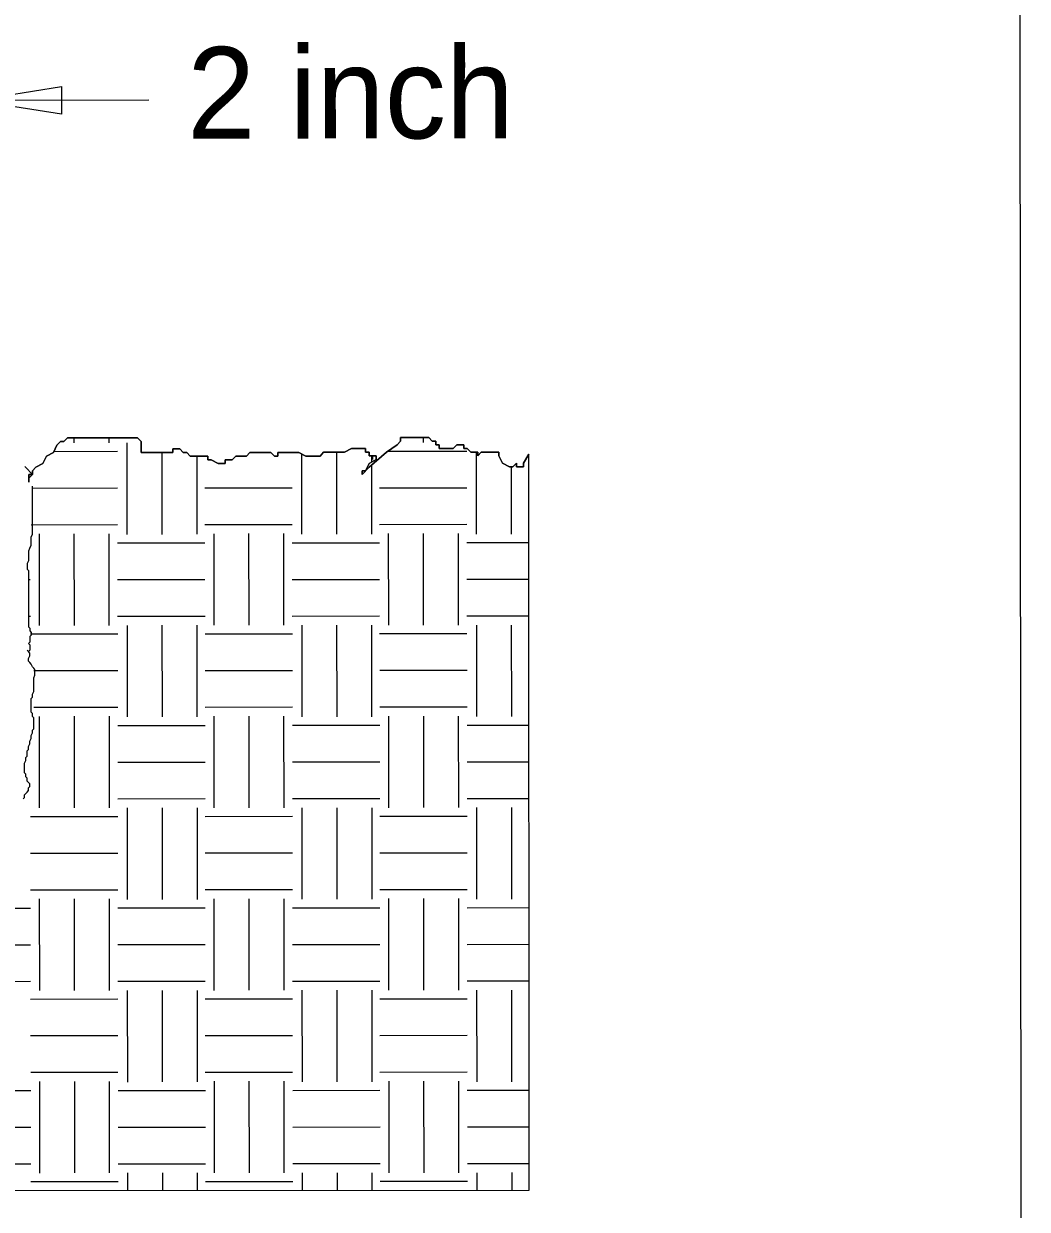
# Model space of a CAD drawing. Extents: x 816132 to 817815, y 885694 to 886789.
# Drawn here: x 816943.9 to 817017.4, y 886385.8 to 886472.6 of the extents above; entities that cross this region are included whole.
import ezdxf

# ---------------------------------------------------------------- set-up
doc = ezdxf.new("R2010")
doc.units = 0
doc.layers.add('Silt Fence Coir Fiber Wattle Break Detail CELL', color=7, linetype='Continuous')

msp = doc.modelspace()

# ---------------------------------------------------------------- linework, layer by layer
at = {"layer": 'Silt Fence Coir Fiber Wattle Break Detail CELL'}
for p, q in [((817017.371, 885756.766), (817016.667, 886743.224)), ((816953.074, 886467.002), (816940.291, 886466.992)), ((816947.593, 886442.299), (816947.594, 886441.931)), ((816950.15, 886442.301), (816950.15, 886441.932)), ((816951.475, 886441.934), (816951.48, 886435.229)), ((816973.158, 886442.32), (816973.158, 886441.951)), ((816946.142, 886441.306), (816950.79, 886441.309)), ((816954.032, 886441.226), (816954.036, 886435.231)), ((816956.589, 886440.959), (816956.593, 886435.234)), ((816964.258, 886441.133), (816964.262, 886435.239)), ((816966.815, 886441.236), (816966.819, 886435.242)), ((816969.371, 886440.969), (816969.371, 886440.52)), ((816970.607, 886441.326), (816976.354, 886441.33)), ((816977.04, 886441.244), (816977.044, 886435.25)), ((816980.917, 886387.232), (816980.879, 886441.113)), ((816969.371, 886440.304), (816969.375, 886435.244)), ((816979.597, 886440.169), (816979.6, 886435.252)), ((816944.532, 886438.623), (816950.792, 886438.628)), ((816957.183, 886438.634), (816963.574, 886438.638)), ((816969.965, 886438.643), (816976.357, 886438.648)), ((816944.458, 886435.941), (816950.793, 886435.946)), ((816957.185, 886435.952), (816963.576, 886435.957)), ((816969.967, 886435.962), (816976.358, 886435.967)), ((816945.042, 886435.272), (816945.047, 886428.568)), ((816947.599, 886435.273), (816947.603, 886428.57)), ((816950.155, 886435.275), (816950.16, 886428.571)), ((816957.825, 886435.281), (816957.829, 886428.578)), ((816960.381, 886435.283), (816960.386, 886428.579)), ((816962.938, 886435.286), (816962.942, 886428.581)), ((816963.577, 886434.615), (816969.968, 886434.62)), ((816970.606, 886435.291), (816970.612, 886428.587)), ((816973.163, 886435.294), (816973.168, 886428.589)), ((816975.719, 886435.296), (816975.724, 886428.592)), ((816976.359, 886434.625), (816980.883, 886434.63)), ((816950.795, 886434.606), (816957.185, 886434.611)), ((816944.345, 886431.919), (816944.406, 886431.919)), ((816950.796, 886431.924), (816957.187, 886431.929)), ((816963.579, 886431.934), (816969.97, 886431.939)), ((816976.361, 886431.944), (816980.885, 886431.948)), ((816944.27, 886429.238), (816944.407, 886429.237)), ((816950.798, 886429.242), (816957.19, 886429.247)), ((816951.484, 886428.572), (816951.489, 886421.868)), ((816954.041, 886428.575), (816954.046, 886421.87)), ((816956.598, 886428.577), (816956.602, 886421.873)), ((816963.58, 886429.252), (816969.972, 886429.257)), ((816964.267, 886428.583), (816964.272, 886421.878)), ((816966.824, 886428.585), (816966.828, 886421.881)), ((816969.38, 886428.586), (816969.385, 886421.883)), ((816976.363, 886429.263), (816980.887, 886429.266)), ((816977.049, 886428.593), (816977.054, 886421.888)), ((816979.605, 886428.595), (816979.611, 886421.891)), ((816944.408, 886427.944), (816950.799, 886427.948)), ((816957.19, 886427.953), (816963.582, 886427.958)), ((816969.973, 886427.964), (816976.364, 886427.969)), ((816944.651, 886425.262), (816950.801, 886425.267)), ((816957.192, 886425.272), (816963.583, 886425.276)), ((816969.975, 886425.282), (816976.366, 886425.287)), ((816944.653, 886422.581), (816950.803, 886422.585)), ((816957.194, 886422.59), (816963.585, 886422.596)), ((816969.976, 886422.601), (816976.368, 886422.606)), ((816945.052, 886421.911), (816945.056, 886415.206)), ((816947.608, 886421.912), (816947.613, 886415.209)), ((816950.164, 886421.914), (816950.169, 886415.21)), ((816957.834, 886421.92), (816957.839, 886415.217)), ((816960.39, 886421.922), (816960.395, 886415.218)), ((816962.947, 886421.924), (816962.952, 886415.22)), ((816970.616, 886421.93), (816970.621, 886415.226)), ((816973.172, 886421.932), (816973.178, 886415.228)), ((816975.729, 886421.935), (816975.734, 886415.23)), ((816950.804, 886421.245), (816957.195, 886421.25)), ((816963.587, 886421.254), (816969.977, 886421.259)), ((816976.369, 886421.264), (816980.893, 886421.268)), ((816950.806, 886418.563), (816957.197, 886418.568)), ((816963.588, 886418.573), (816969.979, 886418.578)), ((816976.371, 886418.583), (816980.895, 886418.587)), ((816950.808, 886415.881), (816957.199, 886415.886)), ((816963.59, 886415.891), (816969.982, 886415.896)), ((816976.372, 886415.901), (816980.896, 886415.905)), ((816951.494, 886415.211), (816951.499, 886408.507)), ((816954.05, 886415.213), (816954.055, 886408.509)), ((816956.607, 886415.216), (816956.612, 886408.511)), ((816964.276, 886415.221), (816964.281, 886408.517)), ((816966.833, 886415.224), (816966.838, 886408.519)), ((816969.39, 886415.225), (816969.394, 886408.522)), ((816977.059, 886415.232), (816977.064, 886408.527)), ((816979.616, 886415.233), (816979.62, 886408.53)), ((816944.418, 886414.582), (816950.809, 886414.587)), ((816957.2, 886414.592), (816963.591, 886414.597)), ((816969.982, 886414.602), (816976.373, 886414.607)), ((816944.42, 886411.901), (816950.811, 886411.906)), ((816957.202, 886411.91), (816963.593, 886411.915)), ((816969.984, 886411.92), (816976.376, 886411.926)), ((816944.421, 886409.219), (816950.812, 886409.224)), ((816957.204, 886409.229), (816963.595, 886409.234)), ((816969.986, 886409.239), (816976.377, 886409.244)), ((816941.4, 886407.875), (816944.423, 886407.879)), ((816945.061, 886408.55), (816945.066, 886401.845)), ((816947.618, 886408.551), (816947.622, 886401.847)), ((816950.174, 886408.553), (816950.179, 886401.849)), ((816950.814, 886407.884), (816957.204, 886407.889)), ((816957.844, 886408.559), (816957.848, 886401.855)), ((816960.4, 886408.561), (816960.405, 886401.857)), ((816962.956, 886408.563), (816962.961, 886401.859)), ((816963.596, 886407.893), (816969.987, 886407.898)), ((816970.626, 886408.569), (816970.631, 886401.865)), ((816973.182, 886408.571), (816973.187, 886401.867)), ((816975.739, 886408.573), (816975.744, 886401.869)), ((816976.379, 886407.903), (816980.902, 886407.907)), ((816938.033, 886405.191), (816944.425, 886405.197)), ((816950.815, 886405.202), (816957.207, 886405.207)), ((816963.598, 886405.212), (816969.989, 886405.217)), ((816976.38, 886405.221), (816980.904, 886405.225)), ((816938.035, 886402.509), (816944.426, 886402.515)), ((816950.818, 886402.52), (816957.209, 886402.525)), ((816963.599, 886402.53), (816969.991, 886402.535)), ((816976.382, 886402.54), (816980.906, 886402.543)), ((816951.504, 886401.85), (816951.508, 886395.146)), ((816954.06, 886401.852), (816954.065, 886395.148)), ((816956.617, 886401.855), (816956.621, 886395.15)), ((816964.286, 886401.86), (816964.291, 886395.156)), ((816966.843, 886401.863), (816966.847, 886395.158)), ((816969.399, 886401.864), (816969.404, 886395.16)), ((816977.069, 886401.871), (816977.073, 886395.166)), ((816979.625, 886401.872), (816979.63, 886395.168)), ((816944.428, 886401.221), (816950.818, 886401.226)), ((816957.209, 886401.231), (816963.601, 886401.236)), ((816969.992, 886401.241), (816976.383, 886401.246)), ((816944.429, 886398.54), (816950.82, 886398.545)), ((816957.212, 886398.549), (816963.603, 886398.554)), ((816969.993, 886398.559), (816976.385, 886398.564)), ((816944.431, 886395.858), (816950.822, 886395.863)), ((816957.213, 886395.868), (816963.604, 886395.873)), ((816969.996, 886395.878), (816976.387, 886395.883)), ((816945.07, 886395.188), (816945.075, 886388.484)), ((816947.627, 886395.19), (816947.632, 886388.486)), ((816950.184, 886395.192), (816950.188, 886388.487)), ((816957.853, 886395.198), (816957.858, 886388.494)), ((816960.41, 886395.2), (816960.414, 886388.495)), ((816962.966, 886395.202), (816962.971, 886388.498)), ((816970.636, 886395.208), (816970.64, 886388.503)), ((816973.192, 886395.21), (816973.197, 886388.506)), ((816975.748, 886395.212), (816975.753, 886388.508)), ((816938.04, 886394.512), (816944.432, 886394.517)), ((816950.823, 886394.522), (816957.215, 886394.527)), ((816963.606, 886394.532), (816969.996, 886394.537)), ((816976.388, 886394.542), (816980.912, 886394.546)), ((816938.043, 886391.83), (816944.434, 886391.835)), ((816950.825, 886391.84), (816957.217, 886391.846)), ((816963.607, 886391.851), (816969.999, 886391.855)), ((816976.39, 886391.86), (816980.913, 886391.864)), ((816938.045, 886389.148), (816944.436, 886389.153)), ((816950.827, 886389.159), (816957.218, 886389.164)), ((816963.609, 886389.169), (816970.001, 886389.174)), ((816976.391, 886389.179), (816980.916, 886389.182)), ((816944.437, 886387.86), (816950.828, 886387.865)), ((816951.513, 886388.489), (816951.514, 886387.208)), ((816954.069, 886388.491), (816954.07, 886387.211)), ((816956.626, 886388.493), (816956.627, 886387.213)), ((816957.219, 886387.87), (816963.61, 886387.875)), ((816964.295, 886388.499), (816964.296, 886387.219)), ((816966.852, 886388.501), (816966.853, 886387.221)), ((816969.409, 886388.503), (816969.409, 886387.222)), ((816970.001, 886387.88), (816976.393, 886387.885)), ((816977.078, 886388.509), (816977.079, 886387.229)), ((816979.635, 886388.511), (816979.635, 886387.23)), ((816904.941, 886387.171), (816980.917, 886387.232))]:
    msp.add_line(p, q, dxfattribs=at)
msp.add_lwpolyline([(816946.683, 886465.991), (816940.291, 886466.992), (816946.682, 886468.002)], close=True, dxfattribs=at)
for points in [[(816943.999, 886440.191), (816944.047, 886440.14), (816944.56, 886439.602), (816944.304, 886439.602), (816944.304, 886439.333), (816944.305, 886439.063), (816944.304, 886439.333), (816944.56, 886439.602), (816944.56, 886439.872), (816944.816, 886440.142), (816945.331, 886440.412), (816945.586, 886440.95), (816946.1, 886441.219), (816946.356, 886441.76), (816946.613, 886442.029), (816946.87, 886442.029), (816947.125, 886442.299), (816947.382, 886442.3), (816947.639, 886442.3), (816948.152, 886442.3), (816948.409, 886442.3), (816948.923, 886442.3), (816949.179, 886442.301), (816949.436, 886442.301), (816949.692, 886442.302), (816949.949, 886442.301), (816950.206, 886442.301), (816950.977, 886442.302), (816951.232, 886442.303), (816951.489, 886442.303), (816951.746, 886442.303), (816952.003, 886442.302), (816952.259, 886442.303), (816952.516, 886442.033), (816952.516, 886441.494), (816952.516, 886441.225), (816952.773, 886441.225), (816953.287, 886441.225), (816953.8, 886441.226), (816954.056, 886441.226), (816954.313, 886441.226), (816954.57, 886441.226), (816954.827, 886441.226), (816954.827, 886441.496), (816955.083, 886441.496), (816955.34, 886441.496), (816955.597, 886441.227), (816955.853, 886441.228), (816956.11, 886440.958), (816956.367, 886440.959), (816956.624, 886440.959), (816956.881, 886440.959), (816957.136, 886440.96), (816957.394, 886440.96), (816957.393, 886440.689), (816957.651, 886440.689), (816958.164, 886440.422), (816958.421, 886440.423), (816958.677, 886440.422), (816958.677, 886440.691), (816958.934, 886440.691), (816959.19, 886440.691), (816959.447, 886440.962), (816959.704, 886440.961), (816959.96, 886440.961), (816960.217, 886440.962), (816960.473, 886441.231), (816960.987, 886441.231), (816961.244, 886441.232), (816961.5, 886441.232), (816961.757, 886441.232), (816962.014, 886441.233), (816962.27, 886440.963), (816962.527, 886440.964), (816962.526, 886441.233), (816962.784, 886441.233), (816963.041, 886441.233), (816963.297, 886441.233), (816963.554, 886441.234), (816963.811, 886441.234), (816964.067, 886441.234), (816964.58, 886440.965), (816964.837, 886440.965), (816965.094, 886440.966), (816965.351, 886440.966), (816965.607, 886440.966), (816965.863, 886441.236), (816966.121, 886441.236), (816966.378, 886441.236), (816966.633, 886441.236), (816966.89, 886441.236), (816967.404, 886441.237), (816967.917, 886441.506)], [(816967.917, 886441.506), (816967.404, 886441.237), (816966.89, 886441.236), (816966.633, 886441.236), (816966.378, 886441.236), (816966.121, 886441.236), (816965.863, 886441.236), (816965.607, 886440.966), (816965.351, 886440.966), (816965.094, 886440.966), (816964.837, 886440.965), (816964.58, 886440.965), (816964.067, 886441.234), (816963.811, 886441.234), (816963.554, 886441.234), (816963.297, 886441.233), (816963.041, 886441.233), (816962.784, 886441.233), (816962.526, 886441.233), (816962.527, 886440.964), (816962.27, 886440.963), (816962.014, 886441.233), (816961.757, 886441.232), (816961.5, 886441.232), (816961.244, 886441.232), (816960.987, 886441.231), (816960.473, 886441.231), (816960.217, 886440.962), (816959.96, 886440.961), (816959.704, 886440.961), (816959.447, 886440.962), (816959.19, 886440.691), (816958.934, 886440.691), (816958.677, 886440.691), (816958.677, 886440.422), (816958.421, 886440.423), (816958.164, 886440.422), (816957.651, 886440.689), (816957.393, 886440.689), (816957.394, 886440.96), (816957.136, 886440.96), (816956.881, 886440.959), (816956.624, 886440.959), (816956.367, 886440.959), (816956.11, 886440.958), (816955.853, 886441.228), (816955.597, 886441.227), (816955.34, 886441.496), (816955.083, 886441.496), (816954.827, 886441.496), (816954.827, 886441.226), (816954.57, 886441.226), (816954.313, 886441.226), (816954.056, 886441.226), (816953.8, 886441.226), (816953.287, 886441.225), (816952.773, 886441.225), (816952.516, 886441.225), (816952.516, 886441.494), (816952.516, 886442.033), (816952.259, 886442.303), (816952.003, 886442.302), (816951.746, 886442.303), (816951.489, 886442.303), (816951.232, 886442.303), (816950.977, 886442.302), (816950.206, 886442.301), (816949.949, 886442.301), (816949.692, 886442.302), (816949.436, 886442.301), (816949.179, 886442.301), (816948.923, 886442.3), (816948.409, 886442.3), (816948.152, 886442.3), (816947.639, 886442.3), (816947.382, 886442.3), (816947.125, 886442.299), (816946.87, 886442.029), (816946.613, 886442.029), (816946.356, 886441.76), (816946.1, 886441.219), (816945.586, 886440.95), (816945.331, 886440.412), (816944.816, 886440.142), (816944.56, 886439.872), (816944.56, 886439.602), (816944.304, 886439.333), (816944.305, 886439.063), (816944.304, 886439.333), (816944.304, 886439.602), (816944.56, 886439.602), (816944.047, 886440.14), (816943.999, 886440.191)], [(816967.917, 886441.506), (816968.43, 886441.507), (816968.686, 886441.506), (816968.944, 886441.508), (816968.944, 886441.238), (816969.201, 886441.238), (816969.201, 886440.969), (816969.201, 886441.238), (816969.201, 886440.969), (816969.458, 886440.969), (816969.458, 886440.699), (816969.458, 886440.969), (816969.714, 886440.97), (816969.714, 886440.699), (816969.201, 886440.43), (816968.945, 886439.891), (816968.688, 886439.891), (816968.688, 886439.621), (816969.201, 886440.16), (816970.484, 886441.239), (816971.254, 886441.779), (816971.51, 886442.048), (816971.51, 886442.318), (816971.767, 886442.319), (816972.28, 886442.319), (816972.536, 886442.319), (816972.794, 886442.319), (816973.05, 886442.319), (816973.306, 886442.32), (816973.564, 886442.32), (816973.82, 886442.05), (816974.076, 886442.05), (816974.077, 886441.781), (816974.334, 886441.781), (816974.335, 886441.511), (816974.591, 886441.512), (816974.848, 886441.512), (816975.361, 886441.512), (816975.617, 886441.782), (816975.874, 886441.782), (816976.13, 886441.783), (816976.13, 886441.513), (816976.388, 886441.513), (816976.644, 886441.244), (816976.901, 886441.244), (816977.158, 886441.244), (816977.158, 886440.975), (816977.414, 886441.245), (816977.671, 886441.245), (816977.928, 886441.245), (816978.184, 886441.245), (816978.44, 886441.245), (816978.698, 886441.246), (816978.698, 886440.976), (816978.955, 886440.439), (816979.469, 886440.169), (816979.725, 886440.169), (816979.981, 886440.439), (816979.981, 886440.169), (816980.24, 886440.169), (816980.495, 886440.169), (816980.495, 886440.44), (816980.879, 886441.113), (816980.879, 886441.113)], [(816980.879, 886441.113), (816980.879, 886441.113), (816980.495, 886440.44), (816980.495, 886440.169), (816980.24, 886440.169), (816979.981, 886440.169), (816979.981, 886440.439), (816979.725, 886440.169), (816979.469, 886440.169), (816978.955, 886440.439), (816978.698, 886440.976), (816978.698, 886441.246), (816978.44, 886441.245), (816978.184, 886441.245), (816977.928, 886441.245), (816977.671, 886441.245), (816977.414, 886441.245), (816977.158, 886440.975), (816977.158, 886441.244), (816976.901, 886441.244), (816976.644, 886441.244), (816976.388, 886441.513), (816976.13, 886441.513), (816976.13, 886441.783), (816975.874, 886441.782), (816975.617, 886441.782), (816975.361, 886441.512), (816974.848, 886441.512), (816974.591, 886441.512), (816974.335, 886441.511), (816974.334, 886441.781), (816974.077, 886441.781), (816974.076, 886442.05), (816973.82, 886442.05), (816973.564, 886442.32), (816973.306, 886442.32), (816973.05, 886442.319), (816972.794, 886442.319), (816972.536, 886442.319), (816972.28, 886442.319), (816971.767, 886442.319), (816971.51, 886442.318), (816971.51, 886442.048), (816971.254, 886441.779), (816970.484, 886441.239), (816969.201, 886440.16), (816968.688, 886439.621), (816968.688, 886439.891), (816968.945, 886439.891), (816969.201, 886440.43), (816969.714, 886440.699), (816969.714, 886440.97), (816969.458, 886440.969), (816969.458, 886440.699), (816969.458, 886440.969), (816969.201, 886440.969), (816969.201, 886441.238), (816969.201, 886440.969), (816969.201, 886441.238), (816968.944, 886441.238), (816968.944, 886441.508), (816968.686, 886441.506), (816968.43, 886441.507), (816967.917, 886441.506)], [(816944.545, 886438.764), (816944.546, 886437.831), (816944.547, 886437.629), (816944.546, 886437.429), (816944.546, 886437.227), (816944.547, 886437.026), (816944.546, 886436.823), (816944.547, 886436.622), (816944.548, 886436.42), (816944.547, 886436.218), (816944.548, 886436.017), (816944.548, 886435.816), (816944.547, 886435.615), (816944.548, 886435.413), (816944.548, 886435.211), (816944.453, 886435.01), (816944.452, 886434.708), (816944.453, 886434.406), (816944.356, 886434.204), (816944.26, 886434.002), (816944.26, 886433.801), (816944.261, 886433.6), (816944.261, 886433.297), (816944.165, 886433.096), (816944.165, 886432.894), (816944.165, 886432.691), (816944.261, 886432.591), (816944.262, 886432.289), (816944.262, 886432.089), (816944.262, 886431.886), (816944.263, 886431.584), (816944.262, 886431.383), (816944.262, 886431.181), (816944.262, 886430.98), (816944.262, 886430.779), (816944.263, 886430.576), (816944.263, 886430.274), (816944.263, 886429.973), (816944.263, 886429.771), (816944.263, 886429.569), (816944.264, 886429.368), (816944.263, 886429.166), (816944.264, 886428.964), (816944.265, 886428.763), (816944.264, 886428.461), (816944.361, 886428.36), (816944.36, 886428.159), (816944.457, 886428.058), (816944.457, 886427.856), (816944.361, 886427.756), (816944.361, 886427.555), (816944.361, 886427.352), (816944.265, 886427.252), (816944.361, 886427.151), (816944.362, 886426.949), (816944.362, 886426.748), (816944.266, 886426.648), (816944.266, 886426.648), (816944.362, 886426.748)], [(816944.266, 886426.144), (816944.362, 886426.346), (816944.362, 886426.547), (816944.266, 886426.648), (816944.17, 886426.748)], [(816944.459, 886425.74), (816944.362, 886425.841), (816944.266, 886425.942), (816944.266, 886426.144)], [(816943.89, 886415.867), (816943.985, 886415.968), (816943.986, 886416.169), (816944.081, 886416.269), (816944.177, 886416.372), (816944.273, 886416.472), (816944.273, 886416.673), (816944.369, 886416.775), (816944.369, 886416.976), (816944.273, 886417.076), (816944.176, 886417.176), (816944.176, 886417.378), (816944.081, 886417.479), (816944.08, 886417.68), (816943.984, 886417.782), (816943.984, 886417.983), (816943.984, 886418.285), (816943.984, 886418.486), (816944.08, 886418.688), (816944.08, 886418.889), (816944.175, 886418.991), (816944.175, 886419.192), (816944.175, 886419.394), (816944.27, 886419.494), (816944.27, 886419.695), (816944.366, 886419.897), (816944.366, 886420.099), (816944.463, 886420.3), (816944.463, 886420.502), (816944.559, 886420.703), (816944.558, 886420.904), (816944.654, 886421.006), (816944.654, 886421.207), (816944.654, 886421.409), (816944.654, 886421.61), (816944.653, 886421.811), (816944.558, 886421.911), (816944.558, 886422.114), (816944.461, 886422.215), (816944.461, 886422.416), (816944.461, 886422.618), (816944.461, 886422.82), (816944.461, 886423.021), (816944.461, 886423.222), (816944.557, 886423.322), (816944.556, 886423.525), (816944.652, 886423.726), (816944.652, 886423.928), (816944.652, 886424.129), (816944.651, 886424.33), (816944.651, 886424.532), (816944.651, 886424.734), (816944.747, 886424.936), (816944.747, 886425.137), (816944.747, 886425.338), (816944.651, 886425.438), (816944.555, 886425.539), (816944.459, 886425.74)]]:
    msp.add_lwpolyline(points, dxfattribs=at)

# ---------------------------------------------------------------- texts
msp.add_text('2 inch', height=6.7041, rotation=0.04504, dxfattribs=at).set_placement((816955.889, 886464.199))

doc.saveas('drawing.dxf')
